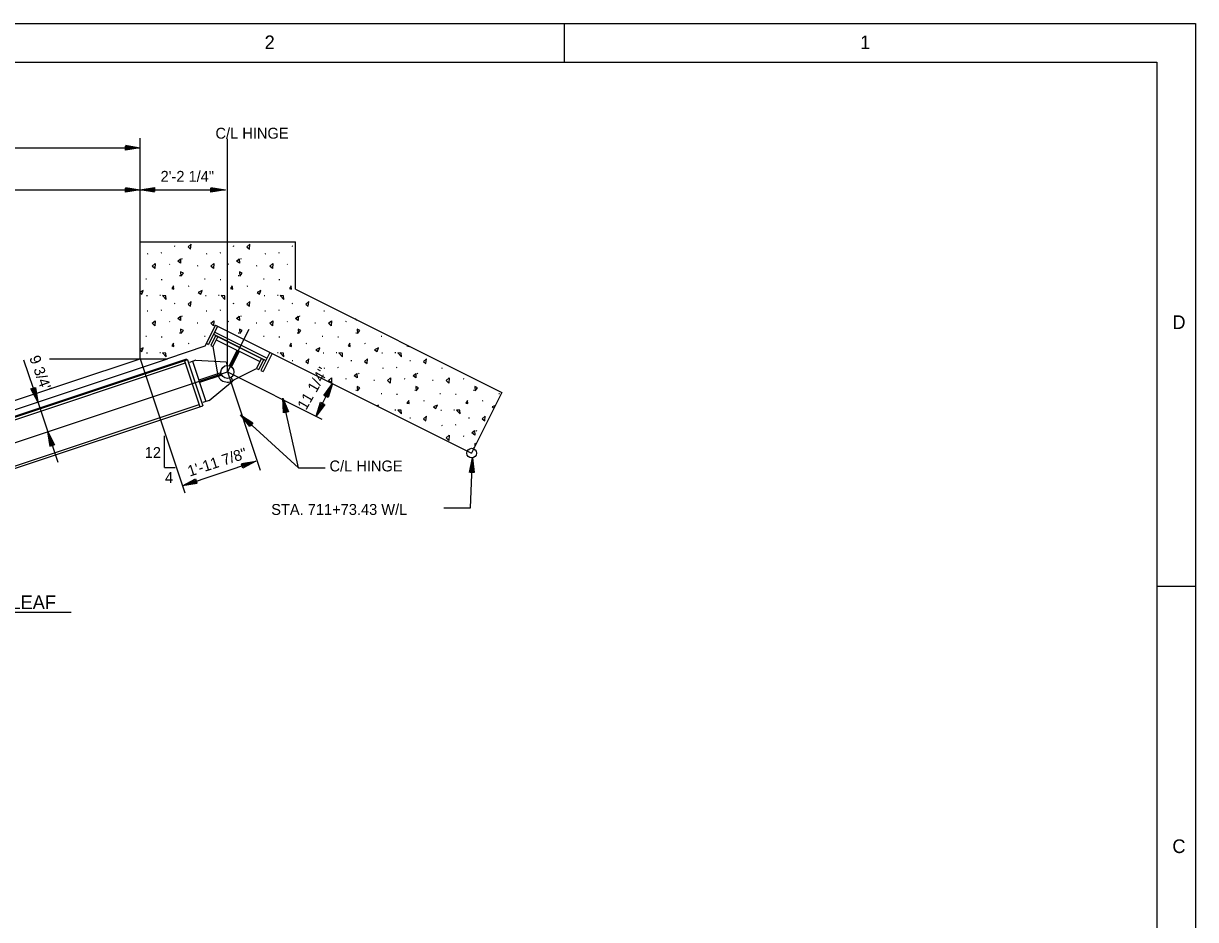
# Model space of a CAD drawing. Extents: x 0.6 to 54, y 0.6 to 38.
# Drawn here: x 33.83 to 53.96, y 22.57 to 37.96 of the extents above; entities that cross this region are included whole.
import ezdxf

# ---------------------------------------------------------------- set-up
doc = ezdxf.new("R2010")
doc.units = 0
for name, color, linetype in [('Level 1', 7, 'Continuous'), ('Level 25', 7, 'Continuous'), ('Level 44', 7, 'Continuous'), ('Level 50', 7, 'Continuous')]:
    doc.layers.add(name, color=color, linetype=linetype)

msp = doc.modelspace()

# ---------------------------------------------------------------- linework, layer by layer
at = {"layer": 'Level 1'}
for p, q in [((43.125, 37.292), (43.125, 37.958)), ((53.292, 28.292), (53.958, 28.292))]:
    msp.add_line(p, q, dxfattribs=at)
for points in [[(0.625, 37.958), (53.958, 37.958), (53.958, 0.625), (0.625, 0.625)], [(2.625, 37.292), (53.292, 37.292), (53.292, 1.292), (2.625, 1.292)]]:
    msp.add_lwpolyline(points, close=True, dxfattribs=at)
at = {"layer": 'Level 25'}
for p, q in [((11.716, 35.824), (35.836, 35.824)), ((35.836, 34.209), (35.836, 35.988)), ((35.836, 34.29), (35.836, 35.979)), ((37.336, 31.972), (37.336, 35.979)), ((23.776, 35.101), (35.836, 35.101)), ((35.836, 35.101), (37.302, 35.101)), ((35.836, 32.199), (35.836, 34.209)), ((35.836, 34.209), (38.503, 34.209)), ((38.503, 33.395), (38.503, 34.209)), ((38.503, 33.395), (42.049, 31.622)), ((37.13, 32.777), (36.948, 32.413)), ((37.13, 32.777), (36.974, 32.465)), ((37.167, 32.758), (37.011, 32.446)), ((37.136, 32.602), (37.049, 32.427)), ((37.099, 32.621), (37.998, 32.171)), ((37.117, 32.658), (38.016, 32.209)), ((37.13, 32.777), (37.167, 32.758)), ((37.13, 32.777), (41.528, 30.578)), ((37.702, 32.703), (37.336, 31.972)), ((36.948, 32.413), (36.305, 32.199)), ((36.974, 32.465), (37.011, 32.446)), ((37.049, 32.427), (37.086, 32.409)), ((37.174, 32.583), (37.086, 32.409)), ((37.133, 32.596), (37.957, 32.184)), ((37.145, 32.527), (37.895, 32.153)), ((37.501, 32.349), (37.366, 32.079)), ((37.539, 32.331), (37.404, 32.06)), ((37.923, 32.209), (37.835, 32.034)), ((38.066, 32.309), (37.91, 31.997)), ((38.104, 32.29), (37.948, 31.978)), ((38.066, 32.309), (38.104, 32.29)), ((36.651, 32.182), (24.097, 27.997)), ((36.632, 32.194), (24.111, 28.02)), ((36.611, 32.125), (24.153, 27.972)), ((33.837, 32.183), (34.079, 31.457)), ((34.28, 32.199), (35.836, 32.199)), ((35.836, 32.199), (36.305, 32.199)), ((35.836, 32.199), (36.603, 29.898)), ((36.598, 32.164), (36.862, 31.374)), ((36.632, 32.194), (36.638, 32.178)), ((36.651, 32.182), (36.915, 31.392)), ((36.791, 32.173), (36.685, 32.137)), ((36.738, 32.155), (36.968, 31.466)), ((37.313, 32.148), (37.334, 32.083)), ((37.835, 32.034), (37.873, 32.015)), ((37.96, 32.19), (37.873, 32.015)), ((37.225, 31.957), (36.846, 31.831)), ((37.238, 31.917), (36.859, 31.791)), ((37.336, 31.972), (37.899, 30.283)), ((37.336, 31.972), (38.957, 31.161)), ((37.402, 31.881), (37.423, 31.817)), ((37.91, 31.997), (37.948, 31.978)), ((38.858, 31.211), (39.139, 31.773)), ((42.049, 31.622), (41.528, 30.578)), ((34.079, 31.457), (34.251, 30.943)), ((37.021, 31.484), (36.915, 31.449)), ((38.555, 30.326), (38.287, 31.524)), ((38.555, 30.326), (37.562, 31.235)), ((34.251, 30.943), (34.424, 30.424)), ((36.253, 30.332), (36.253, 30.878)), ((36.566, 30.018), (37.825, 30.438)), ((36.253, 30.332), (36.436, 30.332)), ((38.555, 30.326), (39.015, 30.326)), ((41.049, 29.64), (41.509, 29.64)), ((32.406, 27.844), (34.655, 27.844))]:
    msp.add_line(p, q, dxfattribs=at)
msp.add_circle((37.336, 31.972), 0.112, dxfattribs=at)
msp.add_arc((37.336, 31.972), 0.174, 179.707, 308.3224, dxfattribs=at)
at = {"layer": 'Level 44'}
for p, q in [((36.205, 34.016), (36.195, 34.012)), ((36.44, 34.129), (36.427, 34.131)), ((37.215, 34.016), (37.205, 34.012)), ((37.45, 34.129), (37.437, 34.131)), ((38.225, 34.016), (38.215, 34.012)), ((38.46, 34.129), (38.447, 34.131)), ((35.972, 34.002), (35.959, 33.998)), ((36.349, 33.817), (36.339, 33.822)), ((36.567, 33.91), (36.556, 33.916)), ((36.982, 34.002), (36.969, 33.998)), ((37.359, 33.817), (37.349, 33.822)), ((37.577, 33.91), (37.566, 33.916)), ((37.992, 34.002), (37.979, 33.998)), ((38.369, 33.817), (38.359, 33.822)), ((36.522, 33.622), (36.512, 33.623)), ((36.829, 33.793), (36.818, 33.792)), ((37.532, 33.622), (37.522, 33.623)), ((37.839, 33.793), (37.828, 33.792)), ((35.945, 33.564), (35.935, 33.566)), ((36.214, 33.555), (36.201, 33.555)), ((36.672, 33.446), (36.66, 33.44)), ((36.955, 33.564), (36.945, 33.566)), ((37.224, 33.555), (37.211, 33.555)), ((37.682, 33.446), (37.67, 33.44)), ((37.965, 33.564), (37.955, 33.566)), ((38.234, 33.555), (38.221, 33.555)), ((35.961, 33.28), (35.948, 33.28)), ((36.185, 33.285), (36.173, 33.285)), ((36.971, 33.28), (36.958, 33.28)), ((37.195, 33.285), (37.183, 33.285)), ((37.981, 33.28), (37.968, 33.28)), ((38.205, 33.285), (38.193, 33.285)), ((35.972, 33.018), (35.959, 33.015)), ((36.205, 33.032), (36.195, 33.028)), ((36.44, 33.145), (36.427, 33.147)), ((36.982, 33.018), (36.969, 33.015)), ((37.215, 33.032), (37.205, 33.028)), ((37.45, 33.145), (37.437, 33.147)), ((37.992, 33.018), (37.979, 33.015)), ((38.225, 33.032), (38.215, 33.028)), ((38.46, 33.145), (38.447, 33.147)), ((39.002, 33.018), (38.989, 33.015)), ((39.232, 33.031), (39.225, 33.028)), ((36.349, 32.833), (36.339, 32.838)), ((36.567, 32.926), (36.556, 32.933)), ((36.829, 32.809), (36.818, 32.808)), ((37.359, 32.833), (37.349, 32.838)), ((37.577, 32.926), (37.566, 32.933)), ((37.839, 32.809), (37.828, 32.808)), ((38.369, 32.833), (38.359, 32.838)), ((38.587, 32.926), (38.576, 32.933)), ((38.849, 32.809), (38.838, 32.808)), ((39.379, 32.833), (39.369, 32.838)), ((36.522, 32.639), (36.512, 32.639)), ((37.532, 32.639), (37.522, 32.639)), ((38.542, 32.639), (38.532, 32.639)), ((39.552, 32.639), (39.542, 32.639)), ((35.945, 32.58), (35.935, 32.582)), ((36.214, 32.572), (36.201, 32.572)), ((36.672, 32.462), (36.66, 32.456)), ((36.955, 32.58), (36.945, 32.582)), ((37.965, 32.58), (37.955, 32.582)), ((38.234, 32.572), (38.221, 32.572)), ((38.692, 32.462), (38.68, 32.456)), ((38.975, 32.58), (38.965, 32.582)), ((39.244, 32.572), (39.231, 32.572)), ((39.702, 32.462), (39.69, 32.456)), ((39.985, 32.58), (39.975, 32.582)), ((35.961, 32.296), (35.948, 32.296)), ((36.185, 32.301), (36.173, 32.301)), ((38.205, 32.301), (38.193, 32.301)), ((38.991, 32.296), (38.978, 32.296)), ((39.215, 32.301), (39.203, 32.301)), ((40.001, 32.296), (39.988, 32.296)), ((40.225, 32.301), (40.213, 32.301)), ((38.46, 32.161), (38.447, 32.164)), ((39.002, 32.035), (38.989, 32.031)), ((39.235, 32.048), (39.225, 32.044)), ((39.47, 32.161), (39.457, 32.164)), ((40.012, 32.035), (39.999, 32.031)), ((40.245, 32.048), (40.235, 32.044)), ((40.48, 32.161), (40.467, 32.164)), ((41.022, 32.035), (41.009, 32.031)), ((39.379, 31.849), (39.369, 31.854)), ((39.597, 31.942), (39.586, 31.949)), ((39.859, 31.825), (39.848, 31.824)), ((40.389, 31.849), (40.379, 31.854)), ((40.607, 31.942), (40.596, 31.949)), ((40.869, 31.825), (40.858, 31.824)), ((41.399, 31.849), (41.389, 31.854)), ((39.552, 31.655), (39.542, 31.656)), ((39.985, 31.596), (39.975, 31.598)), ((40.562, 31.655), (40.552, 31.656)), ((40.995, 31.596), (40.985, 31.598)), ((41.572, 31.655), (41.562, 31.656)), ((42.005, 31.596), (41.995, 31.598)), ((40.254, 31.588), (40.241, 31.588)), ((40.712, 31.479), (40.7, 31.473)), ((41.264, 31.588), (41.251, 31.588)), ((41.722, 31.479), (41.71, 31.473)), ((40.225, 31.317), (40.213, 31.317)), ((41.011, 31.313), (40.998, 31.313)), ((41.235, 31.317), (41.223, 31.317)), ((40.48, 31.178), (40.467, 31.18)), ((41.022, 31.051), (41.009, 31.047)), ((41.255, 31.064), (41.245, 31.061)), ((41.49, 31.178), (41.477, 31.18)), ((41.399, 30.865), (41.389, 30.87)), ((41.617, 30.958), (41.606, 30.965)), ((41.572, 30.671), (41.562, 30.672)), ((41.509, 29.64), (41.541, 30.496))]:
    msp.add_line(p, q, dxfattribs=at)
for points in [[(36.277, 34.209), (36.284, 34.202), (36.284, 34.209)], [(37.287, 34.209), (37.294, 34.202), (37.294, 34.209)], [(38.297, 34.209), (38.304, 34.202), (38.304, 34.209)], [(35.867, 33.309), (35.891, 33.371), (35.836, 33.344)], [(35.836, 33.331), (35.867, 33.309)], [(39.562, 32.855), (39.521, 32.886)], [(39.561, 32.866), (39.562, 32.855)], [(40.427, 32.433), (40.419, 32.421), (40.456, 32.412)], [(40.456, 32.412), (40.456, 32.419)], [(35.867, 32.326), (35.891, 32.387), (35.836, 32.36)], [(35.836, 32.347), (35.867, 32.326)], [(37.911, 32.387), (37.911, 32.387), (37.91, 32.387)], [(39.117, 31.783), (39.073, 31.824), (39.124, 31.87), (39.12, 31.782)], [(39.922, 31.381), (39.931, 31.403), (39.904, 31.39)], [(41.937, 31.396), (41.884, 31.371), (41.914, 31.351)], [(41.603, 30.73), (41.582, 30.741), (41.585, 30.693)]]:
    msp.add_lwpolyline(points, dxfattribs=at)
for points in [[(36.713, 34.165), (36.662, 34.12), (36.704, 34.084)], [(37.723, 34.165), (37.672, 34.12), (37.714, 34.084)], [(36.089, 33.749), (36.043, 33.791), (36.094, 33.837)], [(36.532, 33.839), (36.484, 33.875), (36.53, 33.916)], [(37.099, 33.749), (37.053, 33.791), (37.104, 33.837)], [(37.542, 33.839), (37.494, 33.875), (37.54, 33.916)], [(38.109, 33.749), (38.063, 33.791), (38.114, 33.837)], [(36.537, 33.619), (36.579, 33.667), (36.532, 33.692)], [(37.547, 33.619), (37.589, 33.667), (37.542, 33.692)], [(36.416, 33.395), (36.409, 33.45), (36.379, 33.404)], [(37.426, 33.395), (37.419, 33.45), (37.389, 33.404)], [(38.436, 33.395), (38.429, 33.45), (38.399, 33.404)], [(36.279, 33.282), (36.219, 33.285), (36.284, 33.218)], [(36.877, 33.309), (36.901, 33.371), (36.834, 33.338)], [(37.289, 33.282), (37.229, 33.285), (37.294, 33.218)], [(37.887, 33.309), (37.911, 33.371), (37.844, 33.338)], [(38.299, 33.282), (38.239, 33.285), (38.304, 33.218)], [(36.713, 33.181), (36.662, 33.136), (36.704, 33.101)], [(37.723, 33.181), (37.672, 33.136), (37.714, 33.101)], [(38.733, 33.181), (38.682, 33.136), (38.724, 33.101)], [(36.089, 32.765), (36.043, 32.808), (36.094, 32.853)], [(36.532, 32.855), (36.484, 32.891), (36.53, 32.932)], [(37.099, 32.765), (37.053, 32.808), (37.104, 32.853)], [(37.542, 32.855), (37.494, 32.891), (37.54, 32.932)], [(38.109, 32.765), (38.063, 32.808), (38.114, 32.853)], [(38.552, 32.855), (38.504, 32.891), (38.55, 32.932)], [(39.119, 32.765), (39.073, 32.808), (39.124, 32.853)], [(36.537, 32.635), (36.579, 32.683), (36.532, 32.709)], [(37.547, 32.635), (37.589, 32.683), (37.542, 32.709)], [(38.557, 32.635), (38.599, 32.683), (38.552, 32.709)], [(39.567, 32.635), (39.609, 32.683), (39.562, 32.709)], [(36.416, 32.412), (36.409, 32.466), (36.379, 32.421)], [(38.436, 32.412), (38.429, 32.466), (38.399, 32.421)], [(39.446, 32.412), (39.439, 32.466), (39.409, 32.421)], [(36.279, 32.298), (36.219, 32.301), (36.284, 32.235)], [(38.299, 32.298), (38.239, 32.301), (38.304, 32.235)], [(38.897, 32.326), (38.921, 32.387), (38.854, 32.355)], [(39.309, 32.298), (39.249, 32.301), (39.314, 32.235)], [(39.907, 32.326), (39.931, 32.387), (39.864, 32.355)], [(40.319, 32.298), (40.259, 32.301), (40.324, 32.235)], [(38.733, 32.197), (38.682, 32.153), (38.724, 32.117)], [(39.743, 32.197), (39.692, 32.153), (39.734, 32.117)], [(40.753, 32.197), (40.702, 32.153), (40.744, 32.117)], [(39.562, 31.871), (39.514, 31.908), (39.56, 31.948)], [(40.129, 31.781), (40.083, 31.824), (40.134, 31.87)], [(40.572, 31.871), (40.524, 31.908), (40.57, 31.948)], [(41.139, 31.781), (41.093, 31.824), (41.144, 31.87)], [(39.567, 31.651), (39.609, 31.699), (39.562, 31.725)], [(40.577, 31.651), (40.619, 31.699), (40.572, 31.725)], [(41.587, 31.651), (41.629, 31.699), (41.582, 31.725)], [(40.456, 31.428), (40.449, 31.483), (40.419, 31.437)], [(40.917, 31.342), (40.941, 31.403), (40.874, 31.371)], [(41.466, 31.428), (41.459, 31.483), (41.429, 31.437)], [(40.319, 31.314), (40.259, 31.317), (40.324, 31.251)], [(40.753, 31.214), (40.702, 31.169), (40.744, 31.133)], [(41.329, 31.314), (41.269, 31.317), (41.334, 31.251)], [(41.763, 31.214), (41.712, 31.169), (41.754, 31.133)], [(41.139, 30.797), (41.093, 30.84), (41.144, 30.886)], [(41.582, 30.888), (41.534, 30.924), (41.58, 30.965)]]:
    msp.add_lwpolyline(points, close=True, dxfattribs=at)
msp.add_circle((41.528, 30.578), 0.0833, dxfattribs=at)
at = {"layer": 'Level 50'}
for p, q in [((35.767, 35.824), (35.767, 35.824)), ((35.836, 35.824), (35.836, 35.824)), ((35.767, 35.101), (35.767, 35.101)), ((35.836, 35.101), (35.836, 35.101)), ((35.836, 35.101), (35.836, 35.101)), ((35.905, 35.101), (35.905, 35.101)), ((37.233, 35.101), (37.233, 35.101)), ((37.302, 35.101), (37.302, 35.101)), ((37.086, 32.409), (37.161, 31.973)), ((23.776, 28.179), (35.836, 32.199)), ((23.776, 28.023), (36.305, 32.199)), ((36.791, 32.173), (37.108, 32.158)), ((37.108, 32.158), (37.313, 32.148)), ((37.444, 31.835), (37.835, 32.034)), ((24.097, 27.559), (37.336, 31.972)), ((37.021, 31.484), (37.423, 31.817)), ((39.108, 31.711), (39.108, 31.711)), ((39.139, 31.773), (39.139, 31.773)), ((24.153, 27.182), (36.848, 31.414)), ((34.057, 31.523), (34.057, 31.523)), ((34.079, 31.457), (34.079, 31.457)), ((38.287, 31.524), (38.287, 31.524)), ((38.302, 31.456), (38.302, 31.456)), ((24.097, 27.12), (36.915, 31.392)), ((37.562, 31.235), (37.562, 31.235)), ((38.858, 31.211), (38.858, 31.211)), ((38.889, 31.273), (38.889, 31.273)), ((37.614, 31.188), (37.614, 31.188)), ((34.251, 30.943), (34.251, 30.943)), ((34.273, 30.878), (34.273, 30.878)), ((37.759, 30.416), (37.759, 30.416)), ((37.825, 30.438), (37.825, 30.438)), ((41.539, 30.427), (41.539, 30.427)), ((41.541, 30.496), (41.541, 30.496)), ((36.566, 30.018), (36.566, 30.018)), ((36.632, 30.04), (36.632, 30.04))]:
    msp.add_line(p, q, dxfattribs=at)
for points in [[(35.587, 35.865), (35.836, 35.824), (35.587, 35.783), (35.587, 35.853), (35.767, 35.824), (35.597, 35.796), (35.597, 35.841), (35.7, 35.824), (35.608, 35.809), (35.608, 35.828), (35.631, 35.824)], [(35.587, 35.142), (35.836, 35.101), (35.587, 35.06), (35.587, 35.13), (35.767, 35.101), (35.597, 35.073), (35.597, 35.118), (35.7, 35.101), (35.608, 35.086), (35.608, 35.105), (35.631, 35.101)], [(36.085, 35.06), (35.836, 35.101), (36.085, 35.142), (36.085, 35.072), (35.905, 35.101), (36.075, 35.129), (36.075, 35.084), (35.972, 35.101), (36.064, 35.116), (36.064, 35.097), (36.041, 35.101)], [(37.053, 35.142), (37.302, 35.101), (37.053, 35.06), (37.053, 35.13), (37.233, 35.101), (37.063, 35.073), (37.063, 35.118), (37.166, 35.101), (37.074, 35.086), (37.074, 35.105), (37.097, 35.101)], [(34.04, 31.707), (34.079, 31.457), (33.961, 31.681), (34.028, 31.703), (34.057, 31.523), (33.977, 31.675), (34.02, 31.689), (34.036, 31.586), (33.993, 31.669), (34.011, 31.675), (34.014, 31.652)], [(38.99, 31.568), (39.139, 31.773), (39.064, 31.531), (39.001, 31.563), (39.108, 31.711), (39.057, 31.547), (39.017, 31.567), (39.078, 31.651), (39.05, 31.562), (39.033, 31.57), (39.047, 31.589)], [(38.301, 31.27), (38.287, 31.524), (38.382, 31.289), (38.313, 31.273), (38.302, 31.456), (38.367, 31.296), (38.322, 31.286), (38.317, 31.391), (38.351, 31.304), (38.333, 31.3), (38.332, 31.323)], [(39.006, 31.415), (38.858, 31.211), (38.932, 31.452), (38.996, 31.421), (38.889, 31.273), (38.94, 31.437), (38.98, 31.416), (38.919, 31.332), (38.947, 31.421), (38.963, 31.413), (38.95, 31.394)], [(37.719, 31.036), (37.562, 31.235), (37.775, 31.097), (37.727, 31.044), (37.614, 31.188), (37.758, 31.094), (37.727, 31.061), (37.663, 31.143), (37.741, 31.092), (37.729, 31.078), (37.715, 31.096)], [(34.29, 30.694), (34.251, 30.943), (34.369, 30.72), (34.302, 30.698), (34.273, 30.878), (34.353, 30.726), (34.31, 30.711), (34.294, 30.814), (34.337, 30.732), (34.319, 30.726), (34.316, 30.749)], [(37.575, 30.398), (37.825, 30.438), (37.601, 30.32), (37.579, 30.387), (37.759, 30.416), (37.607, 30.336), (37.593, 30.379), (37.696, 30.395), (37.613, 30.352), (37.607, 30.369), (37.63, 30.373)], [(41.491, 30.248), (41.541, 30.496), (41.573, 30.245), (41.503, 30.248), (41.539, 30.427), (41.56, 30.256), (41.515, 30.258), (41.536, 30.36), (41.547, 30.268), (41.529, 30.268), (41.534, 30.291)], [(36.816, 30.058), (36.566, 30.018), (36.79, 30.136), (36.812, 30.069), (36.632, 30.04), (36.784, 30.12), (36.798, 30.077), (36.695, 30.061), (36.778, 30.104), (36.784, 30.086), (36.761, 30.083)]]:
    msp.add_lwpolyline(points, dxfattribs=at)

# ---------------------------------------------------------------- texts
at = {"layer": 'Level 1'}
for s, p in [('2', (37.974, 37.517)), ('1', (48.2, 37.517)), ('D', (53.56, 32.71)), ('C', (53.56, 23.71))]:
    msp.add_text(s, height=0.234, dxfattribs=at).set_placement(p)
at = {"layer": 'Level 25'}
for s, height, p in [('C/L HINGE', 0.1876, (37.131, 35.979)), ('2\'-2 1/4"', 0.1876, (36.188, 35.238)), ('12', 0.1867, (35.917, 30.495)), ('C/L HINGE', 0.1876, (39.089, 30.264)), ('4', 0.188, (36.263, 30.064)), ('STA. 711+73.43 W/L', 0.1876, (38.088, 29.517)), ('RIGHT LEAF', 0.2333, (32.554, 27.901))]:
    msp.add_text(s, height=height, dxfattribs=at).set_placement(p)
for s, rotation, p in [('9 3/4"', 290, (33.931, 32.216)), ('11 1/4"', 60, (38.686, 31.306)), ('1\'-11 7/8"', 18, (36.688, 30.173))]:
    msp.add_text(s, height=0.1867, rotation=rotation, dxfattribs=at).set_placement(p)

doc.saveas('drawing.dxf')
